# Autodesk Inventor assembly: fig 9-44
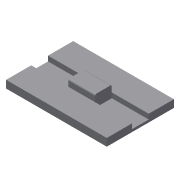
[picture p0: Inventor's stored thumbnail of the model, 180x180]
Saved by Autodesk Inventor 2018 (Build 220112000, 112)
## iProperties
Created: 2013-07
Part Number: fig 9-44
Document SubType Name: Assembly
Designer: CADCIM
Author: CADCIM
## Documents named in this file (3)
- E:\_Deepak\Inventor\Autodesk Inventor_2017_Project\Resources\Inventor_2018_Part\c09_Inv_2018\c09_inv_2018_prt\fig 9-44.iam
- E:\_Deepak\Inventor\Autodesk Inventor_2017_Project\Resources\Inventor_2018_Part\c09_Inv_2018\c09_inv_2018_prt\15.ipt
- E:\_Deepak\Inventor\Autodesk Inventor_2017_Project\Resources\Inventor_2018_Part\c09_Inv_2018\c09_inv_2018_prt\16.ipt
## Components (2 placed, 2 different names)
1. 15:1 — Slider:1
2. 16:1 — Slider:1
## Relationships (1: TranslationJoint 1)
- Slider:1 [TranslationJoint]: 15:1 ↔ 16:1
